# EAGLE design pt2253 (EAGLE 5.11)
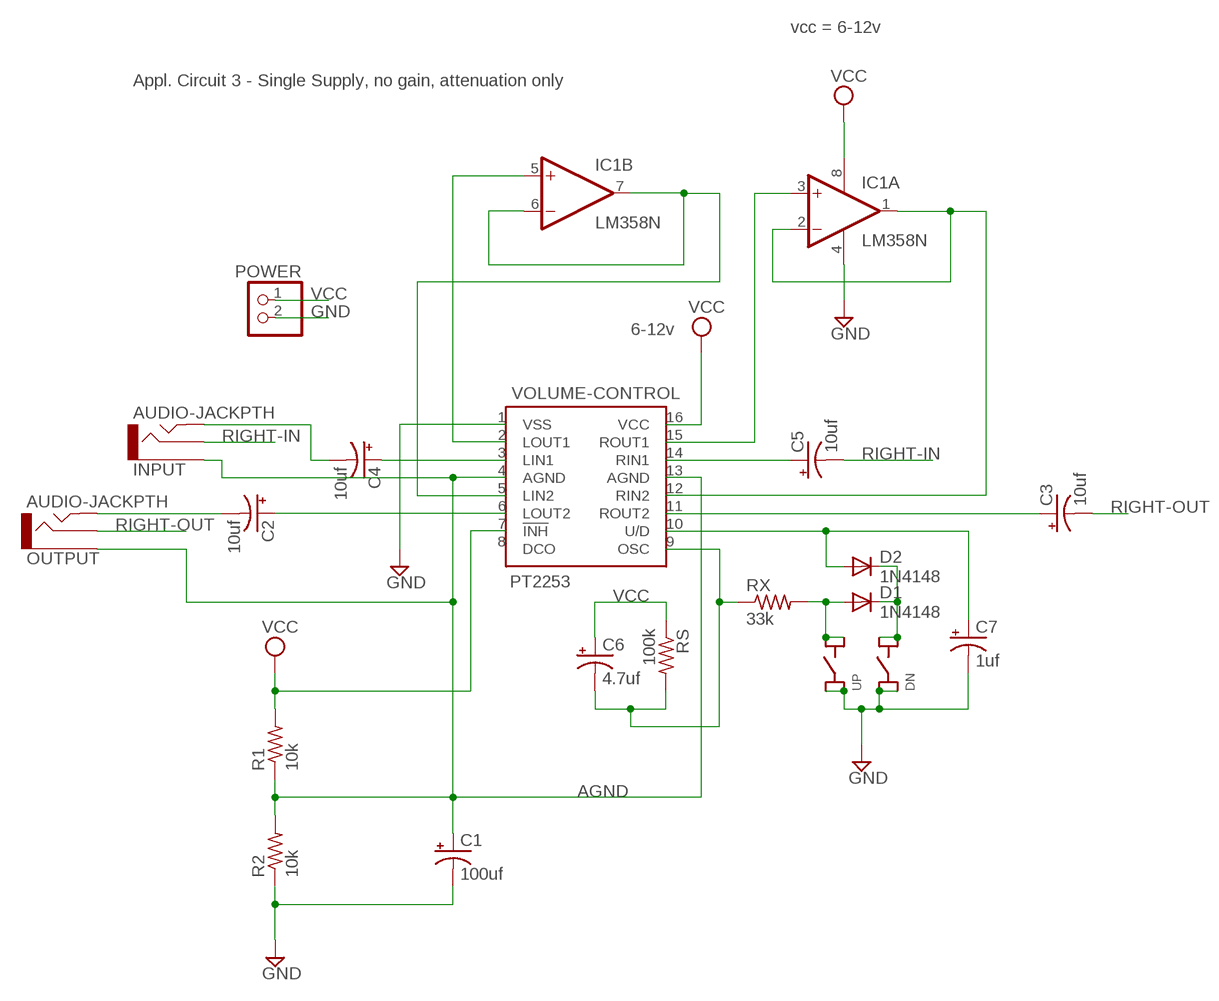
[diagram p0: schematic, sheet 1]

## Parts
C1  100uf  CPOL-USE3.5-8  [E3,5-8]
C2  10uf  CPOL-USE3.5-8  [E3,5-8]
C3  10uf  CPOL-USE3.5-8  [E3,5-8]
C4  10uf  CPOL-USE3.5-8  [E3,5-8]
C5  10uf  CPOL-USE3.5-8  [E3,5-8]
C6  4.7uf  CPOL-USE3.5-8  [E3,5-8]
C7  1uf  CPOL-USE3.5-8  [E3,5-8]
D1  1N4148  1N4148DO35-7  [DO35-7]
D2  1N4148  1N4148DO35-7  [DO35-7]
DN  SFE-PUSHBUTTON-SWITCH  [SFE-PUSHBUTTON-SWITCH]
IC1  LM358N  [DIL08]
INPUT  AUDIO-JACKPTH  [AUDIO-JACK]
OUTPUT  AUDIO-JACKPTH  [AUDIO-JACK]
POWER  PINHD-1X2  [1X02]
R1  10k  R-US_R0805  [R0805]
R2  10k  R-US_R0805  [R0805]
RS  100k  R-US_R0805  [R0805]
RX  33k  R-US_R0805  [R0805]
UP  SFE-PUSHBUTTON-SWITCH  [SFE-PUSHBUTTON-SWITCH]
VOLUME-CONTROL  PT2253  [DIL16-3]

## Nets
AGND: C1.+ INPUT.1 OUTPUT.1 R1.1 R2.2 VOLUME-CONTROL.4(AGND) VOLUME-CONTROL.13(AGND)
GND: C1.- C7.- DN.C@1(C) DN.C@2(C) IC1.4(P:V-) POWER.2 R2.1 UP.C@1(C) UP.C@2(C) VOLUME-CONTROL.1(VSS)
N$1: IC1.1(A:OUT) IC1.2(A:-IN) VOLUME-CONTROL.12(RIN2)
N$2: IC1.6(B:-IN) IC1.7(B:OUT) VOLUME-CONTROL.5(LIN2)
N$3: IC1.5(B:+IN) VOLUME-CONTROL.2(LOUT1)
N$4: C4.- INPUT.5
N$5: C4.+ VOLUME-CONTROL.3(LIN1)
N$6: C2.- OUTPUT.5
N$7: C2.+ VOLUME-CONTROL.6(LOUT2)
N$8: C5.+ VOLUME-CONTROL.14(RIN1)
N$9: C3.+ VOLUME-CONTROL.11(ROUT2)
N$10: IC1.3(A:+IN) VOLUME-CONTROL.15(ROUT1)
N$11: C7.+ D2.A VOLUME-CONTROL.10(U/D)
N$13: D1.C D2.C DN.O@1(O) DN.O@2(O)
N$14: D1.A RX.2 UP.O@1(O) UP.O@2(O)
N$15: C6.- RS.2 RX.1 VOLUME-CONTROL.9(OSC)
RIGHT-IN: C5.- INPUT.2
RIGHT-OUT: C3.- OUTPUT.2
VCC: C6.+ IC1.8(P:V+) POWER.1 R1.2 RS.1 VOLUME-CONTROL.7(!INH) VOLUME-CONTROL.16(VCC)
Unconnected: VOLUME-CONTROL.8(DCO)

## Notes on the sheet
- vcc = 6-12v
- Appl. Circuit 3 - Single Supply, no gain, attenuation only
- 6-12v

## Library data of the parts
C1-C7 = rcl:CPOL-US: POLARIZED CAPACITOR, American symbol
D1 D2 = diode:1N4148: DIODE
DN UP = trl:SFE-PUSHBUTTON-SWITCH
IC1 = linear:LM358: OP AMP also LM158; LM258; LM2904 Source: http://cache.national.com/ds/LM/LM158.pdf
INPUT OUTPUT = SparkFun:AUDIO-JACK: 3.5mm Audio Jack Simple 3.5mm common PCB mount audio jack. SKU: PRT-08032
POWER = pinhead:PINHD-1X2: PIN HEADER
R1 R2 RS RX = resistor:R-US_: RESISTOR, American symbol
VOLUME-CONTROL = trl:PT2253

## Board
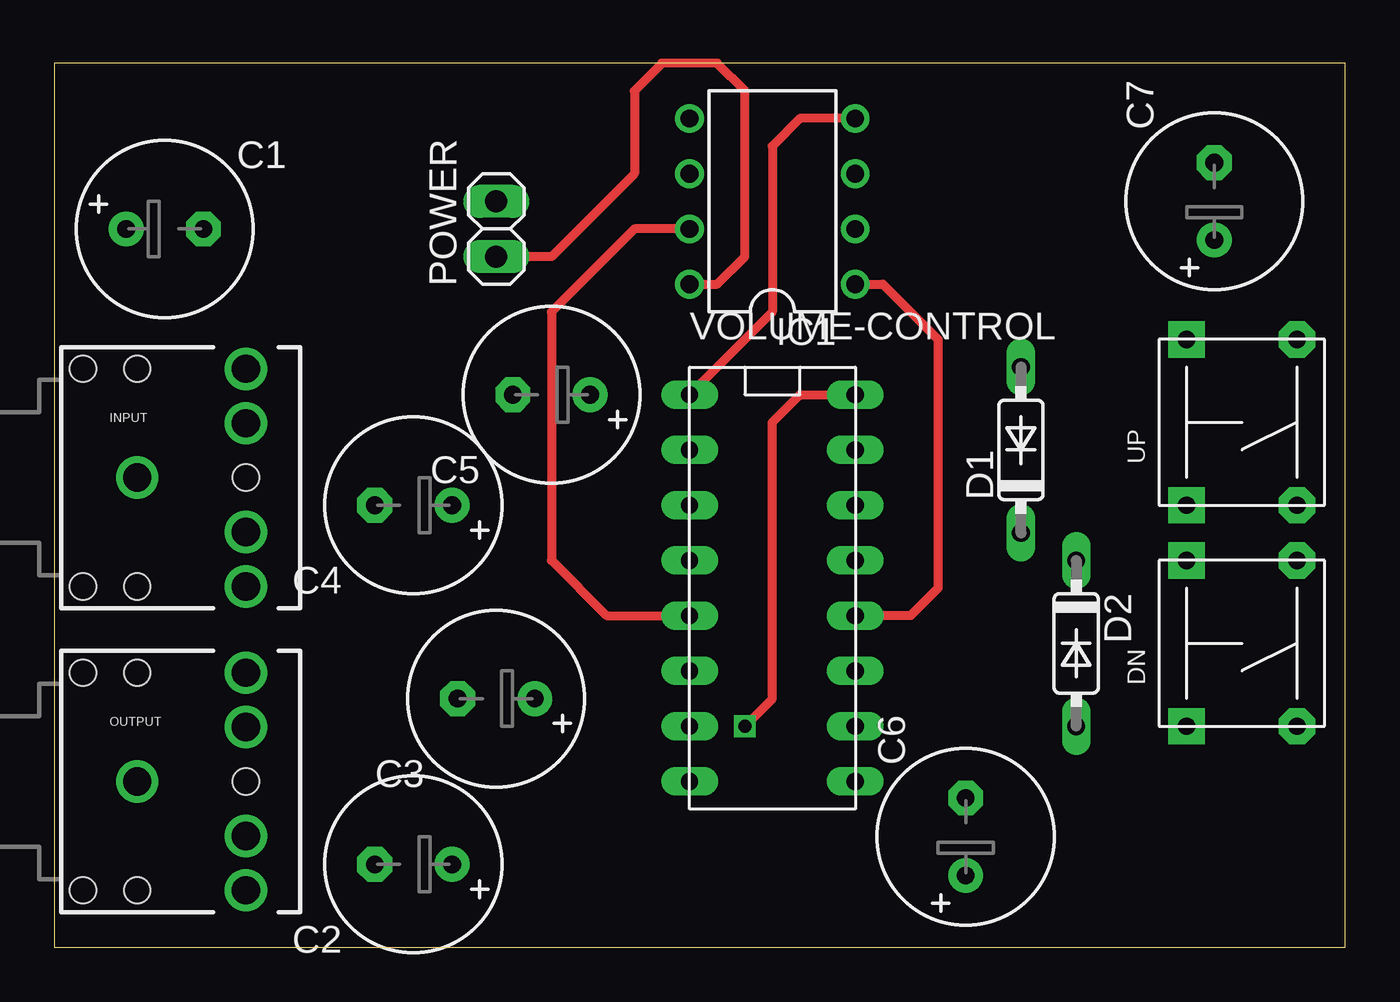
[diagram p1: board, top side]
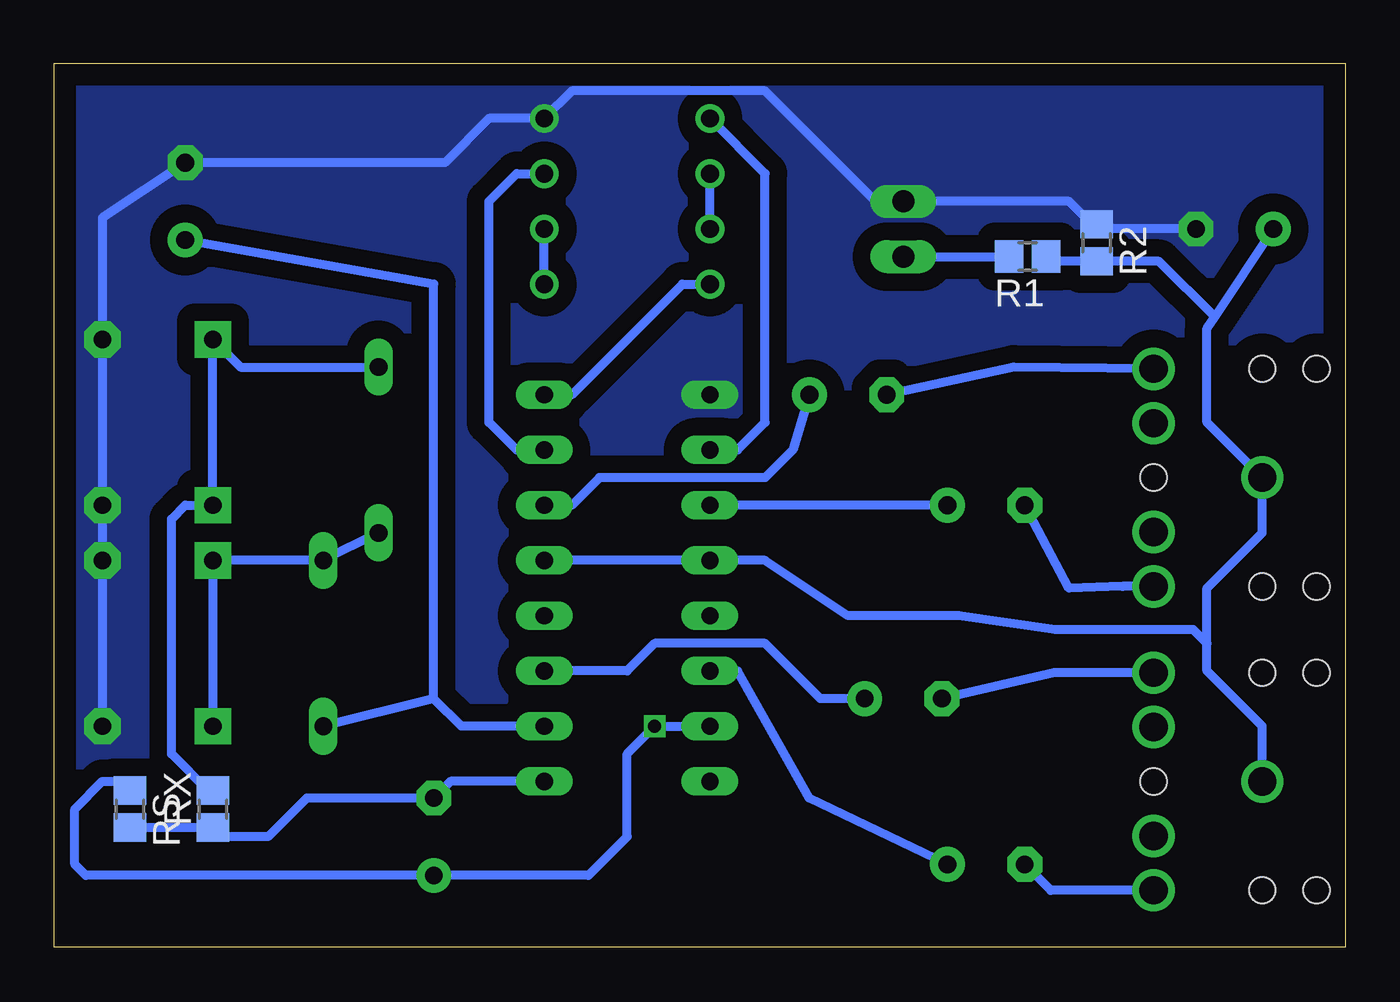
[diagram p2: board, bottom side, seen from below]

Size 59.36 x 40.63 mm. Coordinates in mm from the lower left corner, seen from the top.
Outline: 0,0 59.36,0 59.36,40.63 0,40.63 0,0
Copper layers (1*16): Top 0.035mm / dielectric 1.5mm / Bottom 0.035mm
Design rules "default": minimum track width 10mil, minimum drill 24mil, track to track 8mil, track to pad 8mil, pad to pad 8mil, via to via 8mil, smd to smd 8mil, copper to edge 40mil, drill to drill 8mil, minimum pad ring 10mil, minimum via ring 8mil, stop-mask expansion 4mil, vias tented up to drill 0mil, thermal gap 10mil

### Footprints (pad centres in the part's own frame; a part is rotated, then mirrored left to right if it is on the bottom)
E3,5-8 = drill 0.813 pad 1.6 round: + -1.778,0 | drill 0.813 pad 1.6 octagon: - 1.778,0
DO35-7 = drill 0.813 long: A 3.81,0; C -3.81,0
SFE-PUSHBUTTON-SWITCH = drill 0.8 pad 1.676 octagon: C@1 -3.81,-2.54; C@2 3.81,-2.54 | drill 0.8 pad 1.676 square: O@1 -3.81,2.54; O@2 3.81,2.54
DIL08 = drill 0.813 pad 1.27 round: 1 -3.81,-3.81; 2 -1.27,-3.81; 3 1.27,-3.81; 4 3.81,-3.81; 5 3.81,3.81; 6 1.27,3.81; 7 -1.27,3.81; 8 -3.81,3.81
AUDIO-JACK = drill 1.3 round: 1 0,0; 2 5,5; 3 5,2.5; 4 5,-2.5; 5 5,-5 | hole 1.2: 0,5; -2.5,5; -2.5,-5; 0,-5; 5,0
1X02 = drill 1.016 long: 1 -1.27,0; 2 1.27,0
R0805 = smd 1.3 x 1.5: 1 -0.85,0; 2 0.85,0
DIL16-3 = drill 0.8 long: 1 -3.81,8.89; 2 -3.81,6.35; 3 -3.81,3.81; 4 -3.81,1.27; 5 -3.81,-1.27; 6 -3.81,-3.81; 7 -3.81,-6.35; 8 -3.81,-8.89; 9 3.81,-8.89; 10 3.81,-6.35; 11 3.81,-3.81; 12 3.81,-1.27; 13 3.81,1.27; 14 3.81,3.81; 15 3.81,6.35; 16 3.81,8.89

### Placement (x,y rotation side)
C1  5.08,33.02 0 top
C2  16.51,3.81 180 top
C3  20.32,11.43 180 top
C4  16.51,20.32 180 top
C5  22.86,25.4 180 top
C6  41.91,5.08 90 top
C7  53.34,34.29 90 top
D1  44.45,22.86 90 top
D2  46.99,13.97 270 top
DN  54.61,13.97 90 top
IC1  33.02,34.29 90 top
INPUT  3.81,21.59 0 top
OUTPUT  3.81,7.62 0 top
POWER  20.32,33.02 90 top
R1  14.61,31.75 180 bottom
R2  11.43,32.38 270 bottom
RS  55.88,6.35 270 bottom
RX  52.07,6.35 90 bottom
UP  54.61,24.13 90 top
VOLUME-CONTROL  33.02,16.51 0 top

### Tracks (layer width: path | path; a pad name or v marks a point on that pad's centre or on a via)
AGND
  Bottom 0.406: 6.35,13.97 6.35,12.7 3.81,10.16 OUTPUT.1 | 6.35,13.97 6.35,16.51 3.81,19.05 INPUT.1 6.35,24.13 6.35,28.45 6,28.98 | VOLUME-CONTROL.13 VOLUME-CONTROL.4 26.67,17.78 22.86,15.24 17.78,15.24 13.34,14.61 6.99,14.61 6.35,13.97 | 6,28.98 C1.+ | R1.1 13.54,31.54 R2.2 8.56,31.54 6,28.98
GND
  Top 0.406: VOLUME-CONTROL.1 33.02,29.21 33.02,36.83 34.29,38.1 IC1.4
  Bottom 0.406: DN.C@1 DN.C@2 UP.C@1 UP.C@2 57.15,33.53 C7.- 41.4,36.07 39.37,38.1 IC1.4 35.56,39.37 26.67,39.37 21.59,34.29 POWER.2 12.7,34.29 11.64,33.23 R2.1 11.21,33.02 C1.-
  pour Bottom (isolate 0.813, no thermals): 0,40.64 59.69,40.64 59.69,0 0,0
N$1
  Top 0.406: IC1.1 38.1,30.48 40.64,27.94 40.64,16.51 39.37,15.24 VOLUME-CONTROL.12
  Bottom 0.406: IC1.1 IC1.2
N$2
  Top 0.406: IC1.7 26.67,33.02 22.86,29.21 22.86,17.78 25.4,15.24 VOLUME-CONTROL.5
  Bottom 0.406: IC1.7 IC1.6
N$3
  Bottom 0.406: IC1.5 26.67,35.56 26.67,24.13 27.94,22.86 VOLUME-CONTROL.2
N$4
  Bottom 0.406: INPUT.5 10.24,16.59 12.7,16.51 C4.-
N$5
  Bottom 0.406: C4.+ VOLUME-CONTROL.3
N$6
  Bottom 0.406: OUTPUT.5 13.54,2.62 C2.-
N$7
  Bottom 0.406: C2.+ 24.64,6.86 27.94,12.7 VOLUME-CONTROL.6
N$8
  Bottom 0.406: C5.+ 25.4,22.86 26.67,21.59 34.29,21.59 35.56,20.32 VOLUME-CONTROL.14
N$9
  Bottom 0.406: C3.+ 24.13,11.43 26.67,13.97 31.75,13.97 33.02,12.7 VOLUME-CONTROL.11
N$10
  Bottom 0.406: VOLUME-CONTROL.15 38.1,22.86 39.37,24.13 39.37,34.29 38.1,35.56 IC1.3
N$11
  Bottom 0.406: C7.+ 41.91,30.48 41.91,11.43 | 41.91,11.43 D2.A | VOLUME-CONTROL.10 40.64,10.16 41.91,11.43
N$13
  Bottom 0.406: D1.C D2.C DN.O@2 DN.O@1
N$14
  Bottom 0.406: RX.2 52.28,7.2 53.98,8.89 53.98,19.68 53.34,20.32 UP.O@1 UP.O@2 50.8,26.67 D1.A
N$15
  Bottom 0.406: VOLUME-CONTROL.9 41.15,7.62 C6.- 47.75,6.86 49.53,5.08 51.65,5.08 RX.1 RS.2
RIGHT-IN
  Bottom 0.406: INPUT.2 15.24,26.67 C5.-
RIGHT-OUT
  Bottom 0.406: OUTPUT.2 13.38,12.62 C3.-
VCC  (via drill 0.6)
  Top 0.406: v31.75,10.16 33.02,11.43 33.02,24.13 34.29,25.4 VOLUME-CONTROL.16 | POWER.1 22.86,31.75 26.67,35.56 26.67,39.37 27.94,40.64 30.48,40.64 31.75,39.37 31.75,31.75 30.48,30.48 IC1.8
  Bottom 0.406: VOLUME-CONTROL.7 v31.75,10.16 33.02,8.89 33.02,5.08 34.8,3.3 C6.+ 57.91,3.3 58.42,3.81 58.42,6.35 57.15,7.62 56.3,7.62 RS.1 | POWER.1 R1.2 | IC1.8 30.48,30.48 35.56,25.4 VOLUME-CONTROL.16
